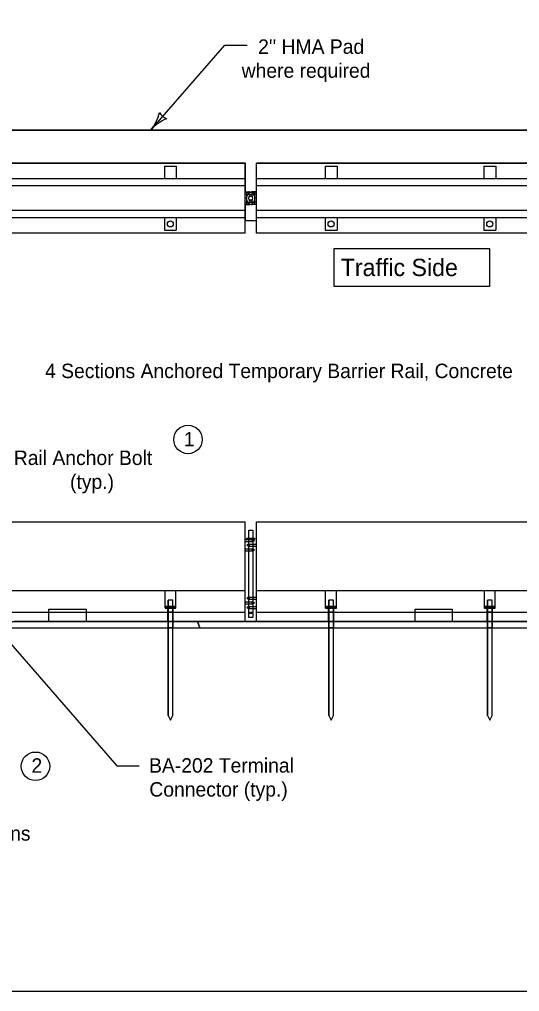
# Model space of a CAD drawing. Extents: x 10028 to 81668, y 3581 to 11018.
# Drawn here: x 14423 to 14950, y 7924 to 8948 of the extents above; entities that cross this region are included whole.
import ezdxf

# ---------------------------------------------------------------- set-up
doc = ezdxf.new("R2010")
doc.units = 0
for name, color, linetype in [('conPaving', 7, 'Continuous'), ('dsnCellsNorthArrow', 7, 'Continuous'), ('dsnTextTabulation', 7, 'Continuous'), ('Level 41', 7, 'Continuous'), ('Level 9', 7, 'Continuous'), ('SheetBorder', 7, 'Continuous')]:
    doc.layers.add(name, color=color, linetype=linetype)

msp = doc.modelspace()

# ---------------------------------------------------------------- linework, layer by layer
at = {"layer": 'conPaving'}
for p, q in [((14579.5, 8313.6), (14493.9, 8313.6)), ((14579.9, 8313.6), (14579.5, 8313.6)), ((14579.9, 8307.1), (14579.9, 8313.6)), ((14584.8, 8313.6), (14584.8, 8307.1)), ((14660.7, 8313.6), (14611, 8313.6)), ((14611, 8313.6), (14613.4, 8307.1)), ((14613.4, 8307.1), (14611, 8313.6)), ((14673.1, 8313.6), (14660.7, 8313.6)), ((14748.7, 8313.6), (14673.1, 8313.6)), ((14749.1, 8313.6), (14748.7, 8313.6)), ((14749.1, 8307.1), (14749.1, 8313.6)), ((14754, 8313.6), (14754, 8307.1)), ((14879.3, 8313.6), (14840, 8313.6)), ((14916.2, 8307.1), (14916.2, 8313.6)), ((14921.1, 8313.6), (14921.1, 8307.1)), ((14417.7, 8307.1), (14579.9, 8307.1)), ((14584.8, 8307.1), (14613.4, 8307.1)), ((14613.4, 8307.1), (14749.1, 8307.1)), ((14754, 8307.1), (14916.2, 8307.1)), ((14921.1, 8307.1), (15083.3, 8307.1))]:
    msp.add_line(p, q, dxfattribs=at)
for points in [[(14493.9, 8313.6), (14454.5, 8313.6), (14418.1, 8313.6)], [(14611, 8313.6), (14585.2, 8313.6), (14584.8, 8313.6)], [(14840, 8313.6), (14754.3, 8313.6), (14754, 8313.6)], [(14916.2, 8313.6), (14915.8, 8313.6), (14879.3, 8313.6)], [(15082.9, 8313.6), (14997.3, 8313.6), (14957.9, 8313.6), (14921.5, 8313.6), (14921.1, 8313.6)]]:
    msp.add_lwpolyline(points, dxfattribs=at)
at = {"layer": 'dsnTextTabulation'}
for p, q in [((14561.7, 8831), (14639.6, 8920.4)), ((14639.6, 8920.4), (14663.2, 8920.4)), ((14661, 8796.1), (14169.5, 8796.1)), ((14661, 8722.4), (14661, 8796.1)), ((15164.4, 8796.1), (14672.9, 8796.1)), ((14672.9, 8722.4), (14672.9, 8796.1)), ((14661, 8779.8), (14169.5, 8779.8)), ((14661, 8772.4), (14169.5, 8772.4)), ((15164.4, 8779.8), (14672.9, 8779.8)), ((15164.4, 8772.4), (14672.9, 8772.4)), ((14661, 8746.2), (14169.5, 8746.2)), ((15164.4, 8746.2), (14672.9, 8746.2)), ((14661, 8738.8), (14169.5, 8738.8)), ((15164.4, 8738.8), (14672.9, 8738.8)), ((14661, 8722.4), (14169.5, 8722.4)), ((15164.4, 8722.4), (14672.9, 8722.4)), ((14169.5, 8418.5), (14661, 8418.5)), ((14661, 8313.9), (14661, 8418.5)), ((14672.9, 8313.9), (14672.9, 8418.5)), ((14672.9, 8418.5), (15164.4, 8418.5)), ((14169.5, 8346.4), (14661, 8346.4)), ((14361.8, 8350.1), (14526, 8161.8)), ((14672.9, 8346.4), (15164.4, 8346.4)), ((14169.5, 8323.4), (14661, 8323.4)), ((14454.5, 8326.7), (14493.9, 8326.7)), ((14454.5, 8313.6), (14454.5, 8323.4)), ((14493.9, 8313.6), (14493.9, 8323.4)), ((14672.9, 8323.4), (15164.4, 8323.4)), ((14840, 8326.7), (14879.3, 8326.7)), ((14840, 8313.6), (14840, 8323.4)), ((14879.3, 8313.6), (14879.3, 8323.4)), ((14375.9, 8313.6), (14454.5, 8313.6)), ((14493.9, 8313.6), (14660.7, 8313.6)), ((14673.1, 8313.6), (14840, 8313.6)), ((14879.3, 8313.6), (14957.9, 8313.6)), ((14526, 8161.8), (14549.6, 8161.8))]:
    msp.add_line(p, q, dxfattribs=at)
for centre in [(14600.9, 8505.3), (14440.3, 8161.2)]:
    msp.add_circle(centre, 15, dxfattribs=at)
for centre, radius, start, end in [((14529.3, 8858.6), 42.5, 319.5664, 347.6389), ((14584.8, 8858.1), 16.4, 211.833, 247.2997), ((14594, 8803.5), 42.5, 111.4939, 139.5664)]:
    msp.add_arc(centre, radius, start, end, dxfattribs=at)
at = {"layer": 'Level 41'}
for p, q in [((14576.1, 8793), (14576.1, 8779.8)), ((14576.1, 8793), (14588.6, 8793)), ((14588.6, 8793), (14588.6, 8779.8)), ((14745.2, 8793), (14757.8, 8793)), ((14745.2, 8793), (14745.2, 8779.8)), ((14757.8, 8793), (14757.8, 8779.8)), ((14912.3, 8793), (14924.9, 8793)), ((14912.3, 8793), (14912.3, 8779.8)), ((14924.9, 8793), (14924.9, 8779.8)), ((14661, 8766), (14664.9, 8766)), ((14661, 8763.6), (14664.9, 8763.6)), ((14672.9, 8766), (14668.9, 8766)), ((14672.9, 8763.6), (14668.9, 8763.6)), ((14661, 8755), (14664.9, 8755)), ((14661, 8752.6), (14664.9, 8752.6)), ((14672.9, 8755), (14668.9, 8755)), ((14672.9, 8752.6), (14668.9, 8752.6)), ((14576.1, 8738.8), (14576.1, 8725.5)), ((14588.6, 8738.8), (14588.6, 8725.5)), ((14745.2, 8738.8), (14745.2, 8725.5)), ((14757.8, 8738.8), (14757.8, 8725.5)), ((14912.3, 8738.8), (14912.3, 8725.5)), ((14924.9, 8738.8), (14924.9, 8725.5)), ((14576.1, 8725.5), (14588.6, 8725.5)), ((14745.2, 8725.5), (14757.8, 8725.5)), ((14912.3, 8725.5), (14924.9, 8725.5)), ((14661, 8399.9), (14669.5, 8399.9)), ((14661, 8397.7), (14669.5, 8397.7)), ((14664.4, 8394.9), (14672.9, 8394.9)), ((14661, 8390), (14669.5, 8390)), ((14661, 8387.9), (14669.5, 8387.9)), ((14664.4, 8392.8), (14672.9, 8392.8)), ((14576.7, 8327.8), (14576.7, 8346.4)), ((14588, 8327.8), (14588, 8346.4)), ((14745.8, 8327.8), (14745.8, 8346.4)), ((14757.2, 8327.8), (14757.2, 8346.4)), ((14913, 8327.8), (14913, 8346.4)), ((14924.3, 8327.8), (14924.3, 8346.4)), ((14661, 8334.3), (14669.5, 8334.3)), ((14661, 8332.2), (14669.5, 8332.2)), ((14664.4, 8339.2), (14672.9, 8339.2)), ((14664.4, 8337.1), (14672.9, 8337.1)), ((14576.7, 8327.8), (14588, 8327.8)), ((14579.5, 8313.6), (14579.5, 8327.8)), ((14585.2, 8313.6), (14585.2, 8327.8)), ((14664.4, 8329.4), (14672.9, 8329.4)), ((14664.4, 8327.3), (14672.9, 8327.3)), ((14745.8, 8327.8), (14757.2, 8327.8)), ((14748.7, 8313.6), (14748.7, 8327.8)), ((14754.3, 8313.6), (14754.3, 8327.8)), ((14913, 8327.8), (14924.3, 8327.8)), ((14915.8, 8313.6), (14915.8, 8327.8)), ((14921.5, 8313.6), (14921.5, 8327.8))]:
    msp.add_line(p, q, dxfattribs=at)
for centre, radius in [((14582.3, 8732.2), 3.15), ((14751.5, 8732.2), 3.15), ((14918.6, 8732.2), 3.15), ((14664.4, 8393.9), 1.06), ((14669.5, 8398.8), 1.06), ((14669.5, 8389), 1.06), ((14664.4, 8338.2), 1.06), ((14669.5, 8333.3), 1.06), ((14664.4, 8328.4), 1.06)]:
    msp.add_circle(centre, radius, dxfattribs=at)
for centre, radius, start, end in [((14668.9, 8759.3), 6.68, 90, 270), ((14668.9, 8759.3), 4.33, 90, 270), ((14664.9, 8759.3), 6.68, 270, 90), ((14664.9, 8759.3), 4.33, 270, 90)]:
    msp.add_arc(centre, radius, start, end, dxfattribs=at)
at = {"layer": 'Level 9'}
for p, q in [((14157.6, 8831), (16177.1, 8831)), ((14658, 8831), (14248, 8831)), ((14248, 8796.1), (14661, 8796.1)), ((14661, 8766), (14664.9, 8766)), ((14662.8, 8765.8), (14671, 8765.8)), ((14662.8, 8752.7), (14662.8, 8765.8)), ((14666.4, 8765.8), (14667.5, 8765.8)), ((14668.9, 8766), (14672.9, 8766)), ((14671, 8765.8), (14671, 8752.7)), ((14664.9, 8752.6), (14661, 8752.6)), ((14671, 8752.7), (14662.8, 8752.7)), ((14667.7, 8752.7), (14666.1, 8752.7)), ((14672.9, 8752.6), (14668.9, 8752.6)), ((14661, 8736), (14672.9, 8736)), ((14661, 8736), (14672.9, 8736)), ((14664.9, 8409.7), (14669, 8409.7)), ((14664.9, 8401.5), (14664.9, 8409.7)), ((14669, 8409.7), (14669, 8401.5)), ((14662.8, 8401.5), (14671, 8401.5)), ((14662.8, 8399.9), (14662.8, 8401.5)), ((14671, 8399.9), (14662.8, 8399.9)), ((14664.9, 8317.9), (14664.9, 8399.9)), ((14669, 8399.9), (14669, 8317.9)), ((14671, 8401.5), (14671, 8399.9)), ((14584.8, 8336), (14579.9, 8336)), ((14579.9, 8336), (14579.9, 8329.4)), ((14584.8, 8336), (14579.9, 8336)), ((14579.9, 8214.8), (14579.9, 8336)), ((14584.8, 8329.4), (14584.8, 8336)), ((14584.8, 8214.8), (14584.8, 8336)), ((14754, 8336), (14749.1, 8336)), ((14749.1, 8336), (14749.1, 8329.4)), ((14754, 8336), (14749.1, 8336)), ((14749.1, 8214.8), (14749.1, 8336)), ((14754, 8329.4), (14754, 8336)), ((14754, 8214.8), (14754, 8336)), ((14921.1, 8336), (14916.2, 8336)), ((14916.2, 8336), (14916.2, 8329.4)), ((14921.1, 8336), (14916.2, 8336)), ((14916.2, 8214.8), (14916.2, 8336)), ((14921.1, 8329.4), (14921.1, 8336)), ((14921.1, 8214.8), (14921.1, 8336)), ((14454.5, 8323.4), (14454.5, 8326.7)), ((14454.5, 8323.4), (14493.9, 8323.4)), ((14493.9, 8323.4), (14493.9, 8326.7)), ((14577.4, 8329.4), (14577.4, 8327.8)), ((14579.9, 8329.4), (14577.4, 8329.4)), ((14577.4, 8327.8), (14577.4, 8329.4)), ((14577.4, 8327.8), (14579.5, 8327.8)), ((14579.5, 8327.8), (14579.9, 8327.8)), ((14584.8, 8329.4), (14579.9, 8329.4)), ((14579.9, 8329.4), (14579.9, 8327.8)), ((14579.9, 8327.8), (14579.9, 8329.4)), ((14579.9, 8329.4), (14584.8, 8329.4)), ((14584.8, 8327.8), (14579.9, 8327.8)), ((14579.9, 8327.8), (14579.9, 8323.4)), ((14579.9, 8327.8), (14584.8, 8327.8)), ((14584.8, 8323.4), (14579.9, 8323.4)), ((14579.9, 8323.4), (14579.9, 8313.6)), ((14579.9, 8323.4), (14584.8, 8323.4)), ((14584.8, 8327.8), (14584.8, 8329.4)), ((14584.8, 8329.4), (14584.8, 8327.8)), ((14584.8, 8323.4), (14584.8, 8327.8)), ((14584.8, 8313.6), (14584.8, 8323.4)), ((14746.6, 8329.4), (14746.6, 8327.8)), ((14749.1, 8329.4), (14746.6, 8329.4)), ((14746.6, 8327.8), (14746.6, 8329.4)), ((14746.6, 8327.8), (14748.7, 8327.8)), ((14748.7, 8327.8), (14749.1, 8327.8)), ((14754, 8329.4), (14749.1, 8329.4)), ((14749.1, 8329.4), (14749.1, 8327.8)), ((14749.1, 8327.8), (14749.1, 8329.4)), ((14749.1, 8329.4), (14754, 8329.4)), ((14754, 8327.8), (14749.1, 8327.8)), ((14749.1, 8327.8), (14749.1, 8323.4)), ((14749.1, 8327.8), (14754, 8327.8)), ((14754, 8323.4), (14749.1, 8323.4)), ((14749.1, 8323.4), (14749.1, 8313.6)), ((14749.1, 8323.4), (14754, 8323.4)), ((14754, 8327.8), (14754, 8329.4)), ((14754, 8329.4), (14754, 8327.8)), ((14754, 8323.4), (14754, 8327.8)), ((14754, 8313.6), (14754, 8323.4)), ((14840, 8323.4), (14840, 8326.7)), ((14840, 8323.4), (14879.3, 8323.4)), ((14879.3, 8323.4), (14879.3, 8326.7)), ((14913.7, 8329.4), (14913.7, 8327.8)), ((14916.2, 8329.4), (14913.7, 8329.4)), ((14913.7, 8327.8), (14913.7, 8329.4)), ((14913.7, 8327.8), (14915.8, 8327.8)), ((14915.8, 8327.8), (14916.2, 8327.8)), ((14921.1, 8329.4), (14916.2, 8329.4)), ((14916.2, 8329.4), (14916.2, 8327.8)), ((14916.2, 8327.8), (14916.2, 8329.4)), ((14916.2, 8329.4), (14921.1, 8329.4)), ((14921.1, 8327.8), (14916.2, 8327.8)), ((14916.2, 8327.8), (14916.2, 8323.4)), ((14916.2, 8327.8), (14921.1, 8327.8)), ((14921.1, 8323.4), (14916.2, 8323.4)), ((14916.2, 8323.4), (14916.2, 8313.6)), ((14916.2, 8323.4), (14921.1, 8323.4)), ((14921.1, 8327.8), (14921.1, 8329.4)), ((14921.1, 8329.4), (14921.1, 8327.8)), ((14921.1, 8323.4), (14921.1, 8327.8)), ((14921.1, 8313.6), (14921.1, 8323.4)), ((13834.4, 8313.6), (16709.2, 8313.6)), ((14584.8, 8313.6), (14579.9, 8313.6)), ((14579.9, 8313.6), (14579.9, 8307.1)), ((14579.9, 8313.6), (14584.8, 8313.6)), ((14584.8, 8307.1), (14584.8, 8313.6)), ((14660.7, 8313.6), (14661, 8313.9)), ((14669, 8317.9), (14664.9, 8317.9)), ((14672.9, 8313.9), (14673.1, 8313.6)), ((14754, 8313.6), (14749.1, 8313.6)), ((14749.1, 8313.6), (14749.1, 8307.1)), ((14749.1, 8313.6), (14754, 8313.6)), ((14754, 8307.1), (14754, 8313.6)), ((14921.1, 8313.6), (14916.2, 8313.6)), ((14916.2, 8313.6), (14916.2, 8307.1)), ((14916.2, 8313.6), (14921.1, 8313.6)), ((14921.1, 8307.1), (14921.1, 8313.6)), ((14157.6, 8307.1), (16177.1, 8307.1)), ((14584.8, 8307.1), (14579.9, 8307.1)), ((14579.9, 8307.1), (14579.9, 8214.8)), ((14579.9, 8307.1), (14584.8, 8307.1)), ((14584.8, 8214.8), (14584.8, 8307.1)), ((14754, 8307.1), (14749.1, 8307.1)), ((14749.1, 8307.1), (14749.1, 8214.8)), ((14749.1, 8307.1), (14754, 8307.1)), ((14754, 8214.8), (14754, 8307.1)), ((14921.1, 8307.1), (14916.2, 8307.1)), ((14916.2, 8307.1), (14916.2, 8214.8)), ((14916.2, 8307.1), (14921.1, 8307.1)), ((14921.1, 8214.8), (14921.1, 8307.1)), ((14579.9, 8214.8), (14582.3, 8209.8)), ((14579.9, 8214.8), (14582.3, 8209.8)), ((14582.3, 8209.8), (14584.8, 8214.8)), ((14582.3, 8209.8), (14584.8, 8214.8)), ((14749.1, 8214.8), (14751.5, 8209.8)), ((14749.1, 8214.8), (14751.5, 8209.8)), ((14751.5, 8209.8), (14754, 8214.8)), ((14751.5, 8209.8), (14754, 8214.8)), ((14916.2, 8214.8), (14918.6, 8209.8)), ((14916.2, 8214.8), (14918.6, 8209.8)), ((14918.6, 8209.8), (14921.1, 8214.8)), ((14918.6, 8209.8), (14921.1, 8214.8))]:
    msp.add_line(p, q, dxfattribs=at)
for points in [[(16177.1, 8831), (14843, 8831), (14658, 8831), (14658, 8831)], [(14658, 8831), (14658, 8831), (14658, 8831)], [(14661, 8796.1), (14661, 8779.8), (14661, 8772.4), (14661, 8766)], [(14672.9, 8766), (14672.9, 8772.4), (14672.9, 8779.8), (14672.9, 8796.1)], [(14672.9, 8796.1), (14843, 8796.1), (15164.4, 8796.1)], [(14661, 8752.6), (14661, 8746.2), (14661, 8738.8), (14661, 8736)], [(14672.9, 8736), (14672.9, 8738.8), (14672.9, 8746.2), (14672.9, 8752.6)], [(14577.4, 8329.4), (14587.3, 8329.4), (14587.3, 8327.8), (14577.4, 8327.8)], [(14587.3, 8327.8), (14587.3, 8329.4), (14584.8, 8329.4)], [(14584.8, 8327.8), (14585.2, 8327.8), (14587.3, 8327.8)], [(14746.6, 8329.4), (14756.4, 8329.4), (14756.4, 8327.8), (14746.6, 8327.8)], [(14756.4, 8327.8), (14756.4, 8329.4), (14754, 8329.4)], [(14754, 8327.8), (14754.3, 8327.8), (14756.4, 8327.8)], [(14913.7, 8329.4), (14923.5, 8329.4), (14923.5, 8327.8), (14913.7, 8327.8)], [(14923.5, 8327.8), (14923.5, 8329.4), (14921.1, 8329.4)], [(14921.1, 8327.8), (14921.5, 8327.8), (14923.5, 8327.8)]]:
    msp.add_lwpolyline(points, dxfattribs=at)
msp.add_lwpolyline([(14754.7, 8706.4), (14918.4, 8706.4), (14918.4, 8666.4), (14754.7, 8666.4)], close=True, dxfattribs=at)
for centre, radius in [((14666.9, 8759.3), 2.05), ((14666.9, 8322.9), 1.02)]:
    msp.add_circle(centre, radius, dxfattribs=at)
for centre, start, end in [((14664.9, 8759.3), 77.6043, 90), ((14668.9, 8759.3), 90, 102.3957), ((14664.9, 8759.3), 270, 280.2309), ((14668.9, 8759.3), 259.7691, 270)]:
    msp.add_arc(centre, 6.68, start, end, dxfattribs=at)
at = {"layer": 'SheetBorder'}
msp.add_lwpolyline([(13732.5, 9944), (16867.5, 9944), (16867.5, 7924), (13732.5, 7924)], close=True, dxfattribs=at)

# ---------------------------------------------------------------- texts
at = {"layer": 'dsnCellsNorthArrow'}
for s, height, p in [("2'' HMA Pad", 15.2, (14674.7, 8911.3)), ('where required', 15.2, (14657.4, 8886.1)), ('Traffic Side', 18.24, (14761.7, 8677.3)), ('4 Sections Anchored Temporary Barrier Rail, Concrete', 15.2, (14450.4, 8569.9)), ('Rail Anchor Bolt', 15.2, (14417.5, 8478.4)), ('(typ.)', 15.2, (14476.7, 8453.2)), ('BA-202 Terminal', 15.2, (14559.9, 8154.5)), ('Connector (typ.)', 15.2, (14560.2, 8129.3)), ('Guardrail Sections', 15.2, (14267.9, 8082.9))]:
    msp.add_text(s, height=height, dxfattribs=at).set_placement(p)
at = {"layer": 'dsnTextTabulation'}
for s, p in [('1', (14596.5, 8498)), ('2', (14436.1, 8154.4))]:
    msp.add_text(s, height=15.2, dxfattribs=at).set_placement(p)

doc.saveas('drawing.dxf')
